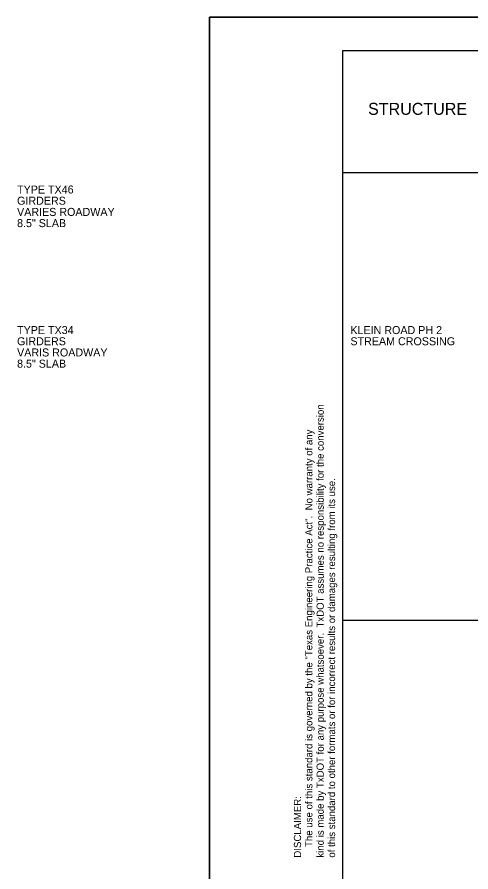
# Model space of a CAD drawing. Extents: x 998.6 to 1033.3, y 1000 to 1011.
# Drawn here: x 998.56 to 1001.96, y 1004.59 to 1011 of the extents above; entities that cross this region are included whole.
import ezdxf

# ---------------------------------------------------------------- set-up
doc = ezdxf.new("R2010")
doc.units = 0
for name, color, linetype in [('D_BATCH_PLOT', 7, 'Continuous'), ('D_SHEET', 7, 'Continuous'), ('Working Level 1', 7, 'Continuous')]:
    doc.layers.add(name, color=color, linetype=linetype)

msp = doc.modelspace()

# ---------------------------------------------------------------- linework, layer by layer
at = {"layer": 'D_BATCH_PLOT'}
msp.add_lwpolyline([(1000, 1000), (1017, 1000), (1017, 1011), (1000, 1011)], close=True, dxfattribs=at)
at = {"layer": 'D_SHEET'}
for p, q in [((1000, 1011), (1017, 1011)), ((1000, 1000), (1000, 1011)), ((1001, 1000.25), (1001, 1010.75)), ((1001, 1010.75), (1016.75, 1010.75))]:
    msp.add_line(p, q, dxfattribs=at)
at = {"layer": 'Working Level 1'}
for p, q in [((1001, 1009.8354), (1005.5117, 1009.8354)), ((1001, 1006.477), (1009.8951, 1006.477))]:
    msp.add_line(p, q, dxfattribs=at)

# ---------------------------------------------------------------- texts
at = {"layer": 'D_SHEET'}
for s, height, p in [('kind is made by TxDOT for any purpose whatsoever.  TxDOT assumes no responsibility for the conversion', 0.0539999, (1000.8561, 1004.6969)), ('    The use of this standard is governed by the "Texas Engineering Practice Act".  No warranty of any', 0.0539999, (1000.7711, 1004.6969)), ('of this standard to other formats or for incorrect results or damages resulting from its use.', 0.054, (1000.9411, 1004.6969)), ('DISCLAIMER:', 0.054, (1000.6861, 1004.6969))]:
    msp.add_text(s, height=height, rotation=90, dxfattribs=at).set_placement(p)
at = {"layer": 'Working Level 1'}
for s, height, p in [('STRUCTURE', 0.09, (1001.1879, 1010.2669)), ('TYPE TX46', 0.06, (998.5582, 1009.6771)), ('GIRDERS', 0.06, (998.5582, 1009.5931)), ('VARIES ROADWAY', 0.06, (998.5582, 1009.5091)), ('8.5" SLAB', 0.06, (998.5582, 1009.4251)), ('TYPE TX34', 0.06, (998.5582, 1008.6231)), ('KLEIN ROAD PH 2', 0.06, (1001.0556, 1008.6231)), ('GIRDERS', 0.06, (998.5582, 1008.5391)), ('STREAM CROSSING', 0.06, (1001.0556, 1008.5391)), ('VARIS ROADWAY', 0.06, (998.5582, 1008.4551)), ('8.5" SLAB', 0.06, (998.5582, 1008.3711))]:
    msp.add_text(s, height=height, dxfattribs=at).set_placement(p)

doc.saveas('drawing.dxf')
